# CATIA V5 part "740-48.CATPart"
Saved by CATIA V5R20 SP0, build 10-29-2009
Part number: 740-48
Bounding box of the stored display mesh (mm): x -39.9 to 39.9, y -37 to 39.9, z -47 to 18
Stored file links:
  C:\Users\Utente\Desktop\IO LAVORO\3D X SITO CF\X SITO\740\740-48.CATPart
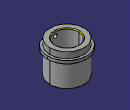
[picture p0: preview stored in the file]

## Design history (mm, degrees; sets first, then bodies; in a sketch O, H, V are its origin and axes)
Set1
  DatumSurface1 to DatumSurface35 "740-48"
Body1 (main body)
